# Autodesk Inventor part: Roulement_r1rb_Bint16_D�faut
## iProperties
Created: 2011-01
Part Number: Roulement_r1rb_Bint16_D�faut
Document SubType Name: Modeling
Designer: eric
Density: 1 g/cm^3
Mass: 0.409986 g
Surface Area: 5.7627 cm^2
Volume: 0.409986 cm^3
Author: eric
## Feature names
1. Base1
